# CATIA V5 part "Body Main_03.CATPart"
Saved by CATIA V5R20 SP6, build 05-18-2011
Part number: Body Main_03
Bounding box of the stored display mesh (mm): x 0 to 100, y -340 to 340, z 0 to 600
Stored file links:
  E:\#03 University\#02 영남 이공대\#01 2021\#02 여름 방학\#01 Documents\K-Move Page02 ASD01\Body Main_03.CATPart
  E:\#03 University\#02 영남 이공대\#01 2021\#02 여름 방학\#01 Documents\K-Move Page02 ASD01\Body Main_01.CATPart
  E:\#03 University\#02 영남 이공대\#01 2021\#02 여름 방학\#01 Documents\K-Move Page02 ASD01\Body Main_02.CATPart
  E:\#03 University\#02 영남 이공대\#01 2021\#02 여름 방학\#01 Documents\K-Move Page02 ASD01\Body Main_04.CATPart

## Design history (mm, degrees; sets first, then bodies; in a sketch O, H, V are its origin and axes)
Set1 "Reference Data"
  Point1 "Center Point": (0, 0, 0)
  DatumCurve1: linked copy from another document
  DatumCurve2: linked copy from another document
Body1 (main body)
  Body2
    Loft1: solid, Sections (DatumCurve2; DatumCurve1), StartSectionTangent yz-plane
  Assemble1: tool Body2
  Shell1: ExtOffset 0, Face (face of Loft1; face of Loft1), IntOffset 5
  Body3 "Upper Pocket Body"
    Sketch1 on xy-plane, origin (0, 0, 0), H (-1, 0, 0), V (0, -1, 0)
      line L1 (0, 250) -> (765.0763, 250)
      line L2 (765.0763, 250) -> (765.0763, -250)
      line L3 (765.0763, -250) -> (0, -250)
      line L4 (-50, -200) -> (-50, 200)
      arc A1 centre (0, 200) radius 50 from (0, 250) to (-50, 200) ccw
      arc A2 centre (0, -200) radius 50 from (0, -250) to (-50, -200) cw
      distance L4 V = 50
      distance L1 L3 = 500
      radius A1 = 50
      radius A2 = 50 {= Sketch1.radius(A1)}
      horizontal: L1 H, L3 H
      vertical: L2 V, L4 V
      symmetry: L1 L3 H
      tangency: A1 L1, A1 L4, A2 L3, A2 L4
    Pad1: profile Sketch1, direction (0, 0, 1), length 800, opposite side length -400
  Remove1: tool Body3
Body4
  Solid1: linked copy from another document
